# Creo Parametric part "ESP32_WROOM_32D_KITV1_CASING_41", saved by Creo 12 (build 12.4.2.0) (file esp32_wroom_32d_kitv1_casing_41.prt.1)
Units: Custom; MM, KILOGRAM, SECS

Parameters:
  PTC_WM_ITERATION = "0"
  PTC_WM_VERSION = "-.0"
  PTC_WM_LIFECYCLE_STATE = "In Work"
  PTC_WM_LIFECYCLE = "MO_CADDocument"
  PTC_WM_CREATED_BY = "Maximilian Roepper (Z0017RMS: MO)"
  PTC_WM_CREATED_ON = "18-Sep-26 11:36:42 AM"
  PTC_WM_MODIFIED_BY = "Maximilian Roepper (Z0017RMS: MO)"
  PTC_WM_MODIFIED_ON = "18-Sep-26 11:36:46 AM"
  PDMLINKNUMBER = "PDM000071455298"
  PTC_WM_NAME = "esp32_wroom_32d_kitv1_casing_41.prt"
  PTC_WM_NUMBER = "PDM000071455298"

Other parameters: WEIGHT, WEIGHT_FACTOR, WEIGHT_ADD, _MASS_TEMP, _DIFF_TEMP, MC_ERRORS, SUPPLIER

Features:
  1. coordinate system
  2. datum plane "PRT_YZ"
  3. datum plane "PRT_XY"
  4. datum plane "PRT_XZ"
  5. coordinate system
  6. datum axis
  7. datum axis
  8. datum axis
  9. coordinate system
  10. imported feature
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
Other named items: PRT, SIEMENS_MO, DRW_VIEW_ORG, PRT_X, PRT_Y, PRT_Z, CS0, ROUGH_GROB

Layers: 00_STD_CSYS-KSYS, 01_STD_PLANES-EBENEN, 02_STD_AXES-ACHSEN, 03_STD_CSYS-KSYS, 24_IMPORT_FEAT-IMPORT_KE

Surfaces: 5 plane, 1 cylinder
